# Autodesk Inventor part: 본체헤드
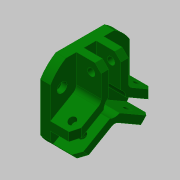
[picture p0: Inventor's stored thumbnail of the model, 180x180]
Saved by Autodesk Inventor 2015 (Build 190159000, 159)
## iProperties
Created: 2020-02
Part Number: 본체헤드
Material: 알루미늄 6061
Document SubType Name: Modeling
Designer: mduedu
Density: 1 g/cm^3
Appearance: 진녹색
Author: mduedu
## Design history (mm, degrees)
sketch "스케치1"
  geometry: L1 (-32, -32)-(32, -32); L2 (32, -32)-(32, 32); L3 (32, 32)-(-32, 32); L4 (-32, 32)-(-32, -32); L5 (-32, -32)-(32, 32); L6 (32, -32)-(-32, 32); 1 further point
  constraints: 12 end point, 2 midpoint, 2 parallel, 1 horizontal, 1 perpendicular
  dimensions: "d0" = 64 distance of L3.end L2.end; "d1" = 64 distance of L2.end L1.end
extrude "돌출1" new body sketch "스케치1" distance "d2" = 28; taper "d3" = 0 deg
sketch "스케치2"
  geometry: C1 r 37.5 at (0, 0); 1 further point
  constraints: 1 centre point, 1 coincident
  dimensions: "d4" = 75 diameter of C1
extrude "돌출2" sketch "스케치2" stored distance "d5" = 28; taper "d6" = 0 deg
sketch "스케치3"
  geometry: C1 r 20 at (0, 0); 1 further point
  constraints: 1 centre point, 1 coincident
  dimensions: "d7" = 40 diameter of C1
extrude "돌출3" join sketch "스케치3" distance "d8" = 12; taper "d9" = 0 deg
sketch "스케치4"
  geometry: L1 (-32, 19.551)-(-32, -19.551) reference; L2 (-19.551, -32)-(19.551, -32) reference; L3 (32, -19.551)-(32, 19.551) reference; L4 (19.551, 32)-(-19.551, 32) reference; L5 (0, 0)-(0, 37.5); L6 (0, 0)-(32.476, -18.75); L7 (0, 0)-(-32.476, -18.75); L8 (11, 6.351)-(11, 35.85); L9 (-11, 6.351)-(-11, 35.85); L10 (-11, 6.351)-(-36.547, -8.399); L11 (0, -12.702)-(-25.547, -27.451); L12 (11, 6.351)-(36.547, -8.399); L13 (0, -12.702)-(25.547, -27.451); L14 (-5, 2.887)-(-5, 37.165); L15 (5, 2.887)-(5, 37.165); L16 (-5, 2.887)-(-34.686, -14.252); L17 (0, -5.774)-(-29.686, -22.913); L18 (0, -5.774)-(29.686, -22.913); L19 (5, 2.887)-(34.686, -14.252); A1 r 37.5 centre (0, 0) between (-19.551, 32) and (-32, 19.551) reference; A2 r 37.5 centre (0, 0) between (-32, -19.551) and (-19.551, -32) reference; A3 r 37.5 centre (0, 0) between (19.551, -32) and (32, -19.551) reference; A4 r 37.5 centre (0, 0) between (32, 19.551) and (19.551, 32) reference; 1 further point
  constraints: 30 end point, 12 parallel, 2 point on circle, 1 coincident, 1 perpendicular, 24 other
  dimensions: "d10" = 120 deg angle of L6 L5; "d11" = 120 deg angle of L7 L6; "d12" = 22 distance between parallel lines of L8 L9; "d14" = 22 distance between parallel lines of L11 L10; "d15" = 22 distance between parallel lines of L12 L13; "d18" = 10 distance between parallel lines of L15 L14; "d19" = 10 distance between parallel lines of L18 L19; "d20" = 10 distance between parallel lines of L16 L17
  node "투영된 루프1"
extrude "돌출4" cut sketch "스케치4" distance "d16" = 20; taper "d17" = 0 deg
extrude "돌출5" cut sketch "스케치4" distance "d21" = 20; taper "d22" = 0 deg
sketch "스케치5"
  geometry: C1 r 9 at (0, 0); 1 further point
  constraints: 1 centre point, 1 coincident
  dimensions: "d23" = 18 diameter of C1
extrude "돌출6" cut sketch "스케치5" stored distance "d24" = 20; taper "d25" = 0 deg
sketch "스케치6"
  geometry: L1 (32, 0)-(19.551, 0) reference; C1 r 3 at (24, 20); 1 further point
  constraints: 1 centre point
  dimensions: "d26" = 6 diameter of C1; "d27" = 24 horizontal distance of C1.centre point (0, 0); "d28" = 20 distance from line of C1.centre L1
extrude "돌출7" cut sketch "스케치6" stored distance "d29" = 20; taper "d30" = 0 deg
sketch "스케치7"
  geometry: L1 (-20, -12)-(-20, 0) reference; L2 (-20, 0)-(-32, 0) reference; L3 (-32, 0)-(-32, 8) reference; L4 (-32, 8)-(-12.702, 8) reference; L5 (-12.702, 8)-(-12.702, 28) reference; L6 (-12.702, 28)-(-9, 28) reference; L7 (-9, 28)-(-9, -12) reference; L8 (-9, -12)-(-20, -12) reference; L9 (20, 0)-(20, -12) reference; L10 (20, -12)-(9, -12) reference; L11 (9, -12)-(9, 8) reference; L12 (9, 8)-(32, 8) reference; L13 (32, 8)-(32, 0) reference; L14 (32, 0)-(20, 0) reference; L15 (20, -8.35)-(17, -8.35); L16 (17, -8.35)-(17, -3.65); L17 (17, -3.65)-(20, -3.65); L18 (20, -3.65)-(20, -8.35); L19 (9, -2.4)-(11, -2.4); L20 (11, -2.4)-(11, -5.6); L21 (11, -5.6)-(9, -5.6); L22 (9, -5.6)-(9, -2.4); L23 (0, -20)-(0, 36) reference; L24 (17, -6)-(20, -6); L25 (11, -4)-(9, -4); 1 further point
  constraints: 20 end point, 4 midpoint, 4 parallel, 2 horizontal, 2 perpendicular, 2 point on line
  dimensions: "d34" = 6 distance between parallel lines of L24 L14; "d35" = 34 diameter of L16 L23; "d36" = 4.7 distance between parallel lines of L17 L15; "d37" = 8 distance between parallel lines of L25 L10; "d38" = 3.2 distance of L19.end L20.end; "d39" = 22 diameter of L20 L23
revolve "회전1" sketch "스케치7" stored, may be unused: angle "d40" = 90 deg
fillet "모깎기1" dims "d41" = 0.8
fillet "모깎기2" dims "d42" = 0.4
chamfer "모따기1" distance "d43" = 0.3; stored, may be unused: second distance "d44" = 2, angle "d45" = 45 deg
chamfer "모따기2" distance "d46" = 0.3; stored, may be unused: second distance "d47" = 2, angle "d48" = 45 deg
chamfer "모따기3" distance "d49" = 1; stored, may be unused: second distance "d50" = 2, angle "d51" = 45 deg
fillet "모깎기3" dims "d52" = 5
chamfer "모따기4" distance "d53" = 5; stored, may be unused: second distance "d54" = 2, angle "d55" = 45 deg
sketch "스케치8" dims "d56" = 52
  geometry: 3 further points
  constraints: 2 vertical alignment, 1 coincident, 2 other
hole "구멍1" sketch "스케치8" at (0, -26) diameter "d57" = 4.5; stored, may be unused: countersink angle "d61" = 90 deg, drill point angle "d63" = 118 deg; dims "d58" = 6, "d59" = 8, "d60" = 4.4, "d62" = 8
node "작업 평면1"
node "작업 평면2"
node "솔리드1"
pattern_circular "원형 패턴1" dims angle "d32" = 360 deg
pattern_circular "원형 패턴2" dims angle "d65" = 360 deg
node "절단 모서리 투영1"
